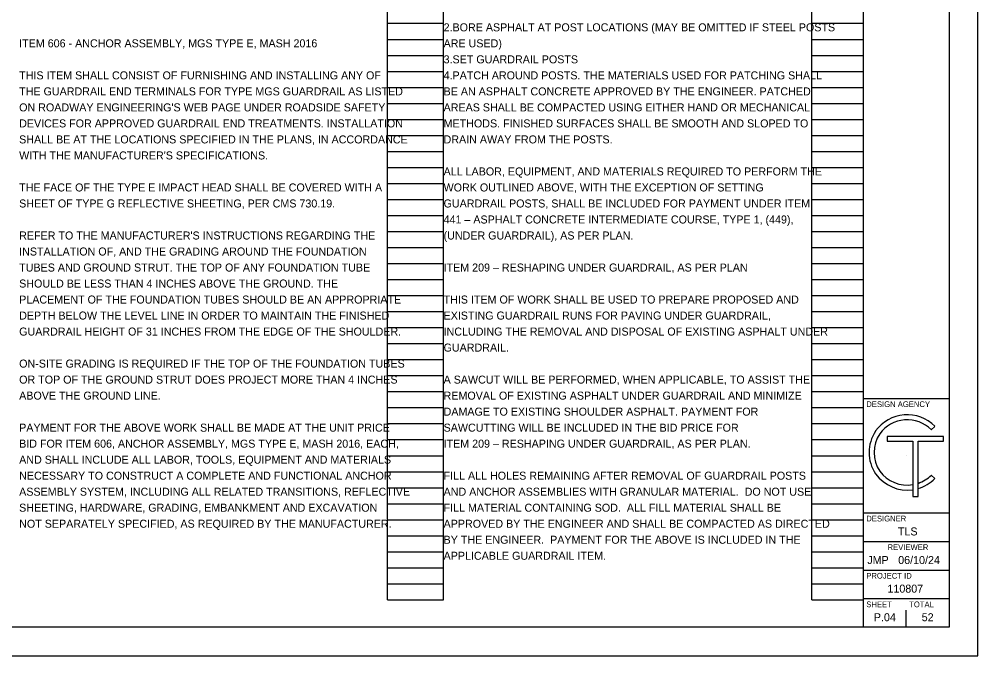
# Model space of a CAD drawing. Extents: x 0 to 53.6, y -30.1 to 32.2.
# Drawn here: x 17.24 to 34, y 0 to 11.13 of the extents above; entities that cross this region are included whole.
import ezdxf

# ---------------------------------------------------------------- set-up
doc = ezdxf.new("R2010")
doc.units = 0
for name, color, linetype in [('SH_Border', 7, 'Continuous'), ('SH_Cut_Line', 7, 'Continuous'), ('SH_Data', 7, 'Continuous'), ('SH_Text', 7, 'Continuous')]:
    doc.layers.add(name, color=color, linetype=linetype)

msp = doc.modelspace()

# ---------------------------------------------------------------- linework, layer by layer
at = {"layer": 'SH_Border'}
for p, q in [((32, 0.5), (32, 21.5)), ((32, 4.5), (33.5, 4.5)), ((32, 2.5), (33.5, 2.5)), ((32, 2), (33.5, 2)), ((32, 1.5), (33.5, 1.5)), ((32, 1), (33.5, 1))]:
    msp.add_line(p, q, dxfattribs=at)
msp.add_lwpolyline([(1.5, 21.5), (33.5, 21.5), (33.5, 0.5), (1.5, 0.5)], close=True, dxfattribs=at)
at = {"layer": 'SH_Cut_Line'}
msp.add_lwpolyline([(0, 0), (34, 0), (34, 22), (0, 22)], close=True, dxfattribs=at)
at = {"layer": 'SH_Data'}
for p, q in [((23.68, 0.98), (23.68, 21.14)), ((24.66, 0.98), (24.66, 21.14)), ((31.1, 0.98), (31.1, 21.14)), ((32, 0.98), (32, 21.14)), ((23.68, 11.06), (24.66, 11.06)), ((31.1, 11.06), (32, 11.06)), ((23.68, 10.78), (24.66, 10.78)), ((31.1, 10.78), (32, 10.78)), ((23.68, 10.5), (24.66, 10.5)), ((31.1, 10.5), (32, 10.5)), ((23.68, 10.22), (24.66, 10.22)), ((31.1, 10.22), (32, 10.22)), ((23.68, 9.94), (24.66, 9.94)), ((31.1, 9.94), (32, 9.94)), ((23.68, 9.66), (24.66, 9.66)), ((31.1, 9.66), (32, 9.66)), ((23.68, 9.38), (24.66, 9.38)), ((31.1, 9.38), (32, 9.38)), ((23.68, 9.1), (24.66, 9.1)), ((31.1, 9.1), (32, 9.1)), ((23.68, 8.82), (24.66, 8.82)), ((31.1, 8.82), (32, 8.82)), ((23.68, 8.54), (24.66, 8.54)), ((31.1, 8.54), (32, 8.54)), ((23.68, 8.26), (24.66, 8.26)), ((31.1, 8.26), (32, 8.26)), ((23.68, 7.98), (24.66, 7.98)), ((31.1, 7.98), (32, 7.98)), ((23.68, 7.7), (24.66, 7.7)), ((31.1, 7.7), (32, 7.7)), ((23.68, 7.42), (24.66, 7.42)), ((31.1, 7.42), (32, 7.42)), ((23.68, 7.14), (24.66, 7.14)), ((31.1, 7.14), (32, 7.14)), ((23.68, 6.86), (24.66, 6.86)), ((31.1, 6.86), (32, 6.86)), ((23.68, 6.58), (24.66, 6.58)), ((31.1, 6.58), (32, 6.58)), ((23.68, 6.3), (24.66, 6.3)), ((31.1, 6.3), (32, 6.3)), ((23.68, 6.02), (24.66, 6.02)), ((31.1, 6.02), (32, 6.02)), ((23.68, 5.74), (24.66, 5.74)), ((31.1, 5.74), (32, 5.74)), ((23.68, 5.46), (24.66, 5.46)), ((31.1, 5.46), (32, 5.46)), ((23.68, 5.18), (24.66, 5.18)), ((31.1, 5.18), (32, 5.18)), ((23.68, 4.9), (24.66, 4.9)), ((31.1, 4.9), (32, 4.9)), ((23.68, 4.62), (24.66, 4.62)), ((31.1, 4.62), (32, 4.62)), ((23.68, 4.34), (24.66, 4.34)), ((31.1, 4.34), (32, 4.34)), ((23.68, 4.06), (24.66, 4.06)), ((31.1, 4.06), (32, 4.06)), ((23.68, 3.78), (24.66, 3.78)), ((31.1, 3.78), (32, 3.78)), ((23.68, 3.5), (24.66, 3.5)), ((31.1, 3.5), (32, 3.5)), ((32.75, 3.5), (32.75, 3.5)), ((23.68, 3.22), (24.66, 3.22)), ((31.1, 3.22), (32, 3.22)), ((23.68, 2.94), (24.66, 2.94)), ((31.1, 2.94), (32, 2.94)), ((23.68, 2.66), (24.66, 2.66)), ((31.1, 2.66), (32, 2.66)), ((23.68, 2.38), (24.66, 2.38)), ((31.1, 2.38), (32, 2.38)), ((23.68, 2.1), (24.66, 2.1)), ((31.1, 2.1), (32, 2.1)), ((23.68, 1.82), (24.66, 1.82)), ((31.1, 1.82), (32, 1.82)), ((23.68, 1.54), (24.66, 1.54)), ((31.1, 1.54), (32, 1.54)), ((23.68, 1.26), (24.66, 1.26)), ((31.1, 1.26), (32, 1.26)), ((23.68, 0.98), (24.66, 0.98)), ((31.1, 0.98), (32, 0.98)), ((32.375, 0.675), (32.375, 0.675)), ((32.75, 0.5), (32.75, 0.8))]:
    msp.add_line(p, q, dxfattribs=at)
at = {"layer": 'SH_Text'}
for p, q in [((33.249, 4.013), (33.187, 3.952)), ((33.249, 4.013), (33.187, 3.952)), ((33.402, 3.833), (32.414, 3.833)), ((32.414, 3.833), (32.414, 3.751)), ((32.414, 3.751), (32.863, 3.751)), ((32.863, 3.751), (32.863, 2.785)), ((32.956, 2.785), (32.956, 3.751)), ((32.956, 3.751), (33.402, 3.751)), ((33.402, 3.751), (33.402, 3.833)), ((33.187, 3.16), (33.249, 3.099)), ((33.187, 3.16), (33.249, 3.099)), ((32.863, 2.993), (32.863, 2.905)), ((32.863, 2.993), (32.863, 2.905)), ((32.956, 2.925), (32.956, 3.016)), ((32.956, 2.925), (32.956, 3.016)), ((32.863, 2.785), (32.956, 2.785))]:
    msp.add_line(p, q, dxfattribs=at)
msp.add_lwpolyline([(32.863, 3.751), (32.863, 2.785), (32.956, 2.785), (32.956, 3.751), (33.402, 3.751), (33.402, 3.833), (32.414, 3.833), (32.414, 3.751)], close=True, dxfattribs=at)
for centre, radius, start, end in [((32.766, 3.535), 0.68, 44.7027, 144.3276), ((32.766, 3.535), 0.68, 44.7027, 144.3276), ((32.766, 3.535), 0.593, 44.7362, 144.1102), ((32.766, 3.535), 0.593, 44.7362, 144.1102), ((32.764, 3.556), 0.666, 145.7329, 214.2671), ((32.764, 3.556), 0.666, 145.7329, 214.2671), ((32.764, 3.556), 0.579, 145.7266, 214.2734), ((32.764, 3.556), 0.579, 145.7266, 214.2734), ((32.766, 3.578), 0.593, 215.8898, 279.4882), ((32.766, 3.578), 0.593, 215.8898, 279.4882), ((32.766, 3.578), 0.68, 215.6724, 278.2613), ((32.766, 3.578), 0.68, 215.6724, 278.2613), ((32.766, 3.578), 0.593, 288.6992, 315.2638), ((32.766, 3.578), 0.593, 288.6992, 315.2638), ((32.766, 3.578), 0.68, 286.2291, 315.2973), ((32.766, 3.578), 0.68, 286.2291, 315.2973)]:
    msp.add_arc(centre, radius, start, end, dxfattribs=at)

# ---------------------------------------------------------------- texts
at = {"layer": 'SH_Data'}
for s, height, p in [('DESIGN AGENCY', 0.1, (32.05, 4.35)), ('DESIGNER', 0.1, (32.05, 2.35)), ('TLS', 0.14, (32.603, 2.105)), ('REVIEWER', 0.1, (32.422, 1.85)), ('JMP', 0.14, (32.068, 1.605)), ('06/10/24', 0.14, (32.608, 1.605)), ('PROJECT ID', 0.1, (32.05, 1.35)), ('110807', 0.14, (32.42, 1.105)), ('SHEET', 0.1, (32.05, 0.85)), ('TOTAL', 0.1, (32.8, 0.85)), ('P.04', 0.14, (32.182, 0.605)), ('52', 0.14, (33.019, 0.605))]:
    msp.add_text(s, height=height, dxfattribs=at).set_placement(p)
at = {"layer": 'SH_Text'}
for s, p in [('2.BORE ASPHALT AT POST LOCATIONS (MAY BE OMITTED IF STEEL POSTS ', (24.66, 10.92)), ('ITEM 606 - ANCHOR ASSEMBLY, MGS TYPE E, MASH 2016', (17.24, 10.64)), ('ARE USED)', (24.66, 10.64)), ('3.SET GUARDRAIL POSTS', (24.66, 10.36)), ('THIS ITEM SHALL CONSIST OF FURNISHING AND INSTALLING ANY OF ', (17.24, 10.08)), ('4.PATCH AROUND POSTS. THE MATERIALS USED FOR PATCHING SHALL ', (24.66, 10.08)), ('THE GUARDRAIL END TERMINALS FOR TYPE MGS GUARDRAIL AS LISTED ', (17.24, 9.8)), ('BE AN ASPHALT CONCRETE APPROVED BY THE ENGINEER. PATCHED ', (24.66, 9.8)), ("ON ROADWAY ENGINEERING'S WEB PAGE UNDER ROADSIDE SAFETY ", (17.24, 9.52)), ('AREAS SHALL BE COMPACTED USING EITHER HAND OR MECHANICAL ', (24.66, 9.52)), ('DEVICES FOR APPROVED GUARDRAIL END TREATMENTS. INSTALLATION ', (17.24, 9.24)), ('METHODS. FINISHED SURFACES SHALL BE SMOOTH AND SLOPED TO ', (24.66, 9.24)), ('SHALL BE AT THE LOCATIONS SPECIFIED IN THE PLANS, IN ACCORDANCE ', (17.24, 8.96)), ('DRAIN AWAY FROM THE POSTS.', (24.66, 8.96)), ("WITH THE MANUFACTURER'S SPECIFICATIONS.", (17.24, 8.68)), ('ALL LABOR, EQUIPMENT, AND MATERIALS REQUIRED TO PERFORM THE ', (24.66, 8.4)), ('THE FACE OF THE TYPE E IMPACT HEAD SHALL BE COVERED WITH A ', (17.24, 8.12)), ('WORK OUTLINED ABOVE, WITH THE EXCEPTION OF SETTING ', (24.66, 8.12)), ('SHEET OF TYPE G REFLECTIVE SHEETING, PER CMS 730.19.', (17.24, 7.84)), ('GUARDRAIL POSTS, SHALL BE INCLUDED FOR PAYMENT UNDER ITEM ', (24.66, 7.84)), ('441 – ASPHALT CONCRETE INTERMEDIATE COURSE, TYPE 1, (449), ', (24.66, 7.56)), ("REFER TO THE MANUFACTURER'S INSTRUCTIONS REGARDING THE ", (17.24, 7.28)), ('(UNDER GUARDRAIL), AS PER PLAN.', (24.66, 7.28)), ('INSTALLATION OF, AND THE GRADING AROUND THE FOUNDATION ', (17.24, 7)), ('TUBES AND GROUND STRUT. THE TOP OF ANY FOUNDATION TUBE ', (17.24, 6.72)), ('ITEM 209 – RESHAPING UNDER GUARDRAIL, AS PER PLAN', (24.66, 6.72)), ('SHOULD BE LESS THAN 4 INCHES ABOVE THE GROUND. THE ', (17.24, 6.44)), ('PLACEMENT OF THE FOUNDATION TUBES SHOULD BE AN APPROPRIATE ', (17.24, 6.16)), ('THIS ITEM OF WORK SHALL BE USED TO PREPARE PROPOSED AND ', (24.66, 6.16)), ('DEPTH BELOW THE LEVEL LINE IN ORDER TO MAINTAIN THE FINISHED ', (17.24, 5.88)), ('EXISTING GUARDRAIL RUNS FOR PAVING UNDER GUARDRAIL, ', (24.66, 5.88)), ('GUARDRAIL HEIGHT OF 31 INCHES FROM THE EDGE OF THE SHOULDER.', (17.24, 5.6)), ('INCLUDING THE REMOVAL AND DISPOSAL OF EXISTING ASPHALT UNDER ', (24.66, 5.6)), ('GUARDRAIL.', (24.66, 5.32)), ('ON-SITE GRADING IS REQUIRED IF THE TOP OF THE FOUNDATION TUBES ', (17.24, 5.04)), ('OR TOP OF THE GROUND STRUT DOES PROJECT MORE THAN 4 INCHES ', (17.24, 4.76)), ('A SAWCUT WILL BE PERFORMED, WHEN APPLICABLE, TO ASSIST THE ', (24.66, 4.76)), ('ABOVE THE GROUND LINE.', (17.24, 4.48)), ('REMOVAL OF EXISTING ASPHALT UNDER GUARDRAIL AND MINIMIZE ', (24.66, 4.48)), ('DAMAGE TO EXISTING SHOULDER ASPHALT. PAYMENT FOR ', (24.66, 4.2)), ('PAYMENT FOR THE ABOVE WORK SHALL BE MADE AT THE UNIT PRICE ', (17.24, 3.92)), ('SAWCUTTING WILL BE INCLUDED IN THE BID PRICE FOR', (24.66, 3.92)), ('BID FOR ITEM 606, ANCHOR ASSEMBLY, MGS TYPE E, MASH 2016, EACH, ', (17.24, 3.64)), ('ITEM 209 – RESHAPING UNDER GUARDRAIL, AS PER PLAN. ', (24.66, 3.64)), ('AND SHALL INCLUDE ALL LABOR, TOOLS, EQUIPMENT AND MATERIALS ', (17.24, 3.36)), ('NECESSARY TO CONSTRUCT A COMPLETE AND FUNCTIONAL ANCHOR ', (17.24, 3.08)), ('FILL ALL HOLES REMAINING AFTER REMOVAL OF GUARDRAIL POSTS ', (24.66, 3.08)), ('ASSEMBLY SYSTEM, INCLUDING ALL RELATED TRANSITIONS, REFLECTIVE ', (17.24, 2.8)), ('AND ANCHOR ASSEMBLIES WITH GRANULAR MATERIAL.  DO NOT USE ', (24.66, 2.8)), ('SHEETING, HARDWARE, GRADING, EMBANKMENT AND EXCAVATION ', (17.24, 2.52)), ('FILL MATERIAL CONTAINING SOD.  ALL FILL MATERIAL SHALL BE ', (24.66, 2.52)), ('NOT SEPARATELY SPECIFIED, AS REQUIRED BY THE MANUFACTURER.', (17.24, 2.24)), ('APPROVED BY THE ENGINEER AND SHALL BE COMPACTED AS DIRECTED ', (24.66, 2.24)), ('BY THE ENGINEER.  PAYMENT FOR THE ABOVE IS INCLUDED IN THE ', (24.66, 1.96)), ('APPLICABLE GUARDRAIL ITEM.', (24.66, 1.68))]:
    msp.add_text(s, height=0.14, dxfattribs=at).set_placement(p)

doc.saveas('drawing.dxf')
